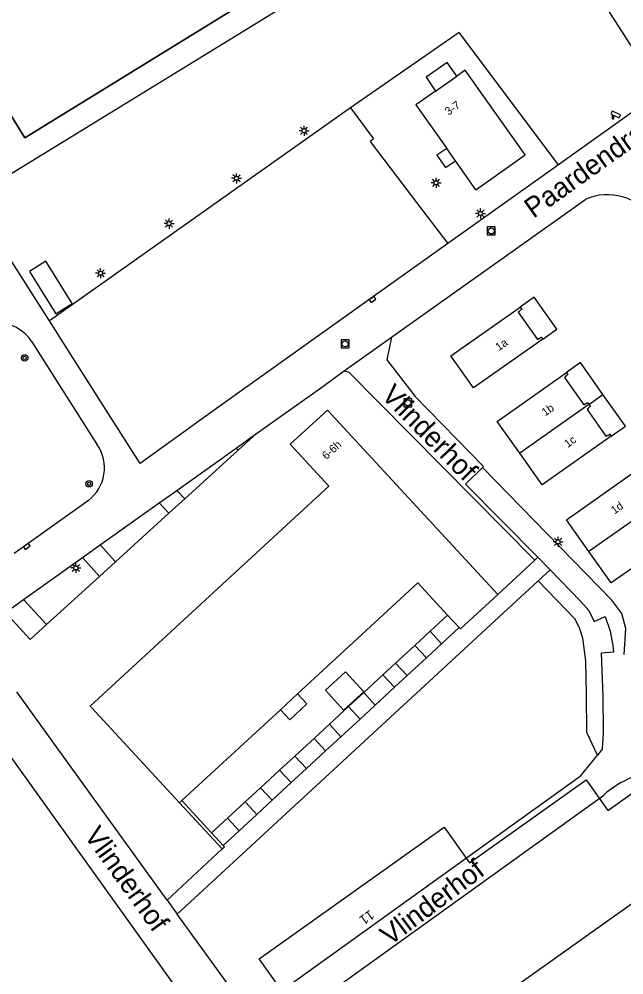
# Model space of a CAD drawing. Extents: x 141000 to 143000, y 400580 to 403500.
# Drawn here: x 141073.5 to 141149.1, y 403024.1 to 403143.4 of the extents above; entities that cross this region are included whole.
import ezdxf

# ---------------------------------------------------------------- set-up
doc = ezdxf.new("R2010")
doc.units = 0
for name, color, linetype in [('gg-afsc-hekwerk', 7, 'Continuous'), ('gg-afsc-muur', 7, 'Continuous'), ('gg-anno-huisnummerreeks BGT', 7, 'Continuous'), ('gg-anno-openbare ruimte label', 7, 'Continuous'), ('gg-bbg-bijgebouw', 7, 'Continuous'), ('gg-bbg-hoofdgebouw', 7, 'Continuous'), ('gg-bbg-luifel en loopbrug', 7, 'Continuous'), ('gg-bbg-tussenscheiding', 7, 'Continuous'), ('gg-knt-verharding', 7, 'Continuous'), ('gg-knt-verharding nz', 7, 'Continuous'), ('gt-anno-plantopografie huisnummer', 7, 'Continuous'), ('gt-bbg-plantopografie pand', 7, 'Continuous'), ('gt-grn-groengrens', 7, 'Continuous'), ('gt-grn-vlakafsluiter', 7, 'Continuous'), ('gt-grn-weggrens', 7, 'Continuous'), ('gt-symb-boom', 7, 'Continuous'), ('gt-symb-camera', 7, 'Continuous'), ('gt-symb-kolk', 7, 'Continuous'), ('gt-symb-lichtmast', 7, 'Continuous'), ('gt-symb-rioolschacht', 7, 'Continuous'), ('gx-grn-maaiveld', 7, 'Continuous')]:
    doc.layers.add(name, color=color, linetype=linetype)

# ---------------------------------------------------------------- blocks, each defined once
blk = doc.blocks.new('gt0-RS')
at = {"layer": 'gt-symb-rioolschacht'}
blk.add_lwpolyline([(-0.5, -0.5), (0.5, -0.5), (0.5, 0.5), (-0.5, 0.5)], close=True, dxfattribs=at)
blk.add_circle((0, 0), 0.375, dxfattribs=at)
blk = doc.blocks.new('gt0-LMAST')
at = {"layer": 'gt-symb-lichtmast'}
for p, q in [((-0.18, 0.17), (-0.45, 0.44)), ((-0.01, 0.25), (-0.01, 0.62)), ((0.17, 0.17), (0.44, 0.44)), ((-0.26, 0), (-0.63, 0)), ((-0.18, -0.18), (-0.45, -0.45)), ((-0.01, -0.25), (-0.01, -0.63)), ((0.44, -0.45), (0.17, -0.18)), ((0.24, 0), (0.62, 0))]:
    blk.add_line(p, q, dxfattribs=at)
blk.add_circle((-0.01, 0), 0.25, dxfattribs=at)
blk = doc.blocks.new('gt0-KOLK')
at = {"layer": 'gt-symb-kolk'}
blk.add_lwpolyline([(0, 0), (0.37, 0), (0.37, 0.4), (-0.38, 0.4), (-0.38, 0), (0, 0)], dxfattribs=at)
blk = doc.blocks.new('gt0-BOOM')
at = {"layer": 'gt-symb-boom'}
for radius in [0.4, 0.2]:
    blk.add_circle((0, 0), radius, dxfattribs=at)
blk = doc.blocks.new('gt0-CAMERA')
at = {"layer": 'gt-symb-camera'}
for points in [[(0.07, 0.48), (0.75, 0.16), (0.92, 0.51), (-0.12, 1), (-0.28, 0.65), (-0.07, 0.55)], [(0.07, 0.48), (0.07, 0), (-0.07, 0), (-0.07, 0.55)]]:
    blk.add_lwpolyline(points, dxfattribs=at)

msp = doc.modelspace()

# ---------------------------------------------------------------- linework, layer by layer
at = {"layer": 'gg-afsc-hekwerk'}
msp.add_lwpolyline([(141060.06, 403151.69), (141094.93, 403173.23), (141109.35, 403150.25), (141074.26, 403128.6), (141060.06, 403151.69)], dxfattribs=at)
at = {"layer": 'gg-afsc-muur'}
for p, q in [((141093.58, 403045.56), (141098.89, 403039.8)), ((141097.58, 403041.82), (141093.87, 403045.84))]:
    msp.add_line(p, q, dxfattribs=at)
msp.add_lwpolyline([(141098.89, 403039.8), (141099.19, 403040.08), (141099.02, 403040.25)], dxfattribs=at)
at = {"layer": 'gg-bbg-bijgebouw'}
for p, q in [((141124.85, 403066.99), (141122.94, 403065.22)), ((141126.3, 403065.42), (141124.85, 403066.99)), ((141122.94, 403065.22), (141124.39, 403063.66)), ((141124.39, 403063.66), (141126.3, 403065.42)), ((141120.55, 403063.01), (141118.97, 403061.56)), ((141121.99, 403061.45), (141120.55, 403063.01)), ((141118.97, 403061.56), (141120.42, 403059.99)), ((141120.42, 403059.99), (141121.99, 403061.45)), ((141116.58, 403059.35), (141114.67, 403057.59)), ((141118.02, 403057.78), (141116.58, 403059.35)), ((141114.67, 403057.59), (141116.11, 403056.02)), ((141116.11, 403056.02), (141118.02, 403057.78)), ((141112.28, 403055.38), (141110.37, 403053.62)), ((141113.72, 403053.82), (141112.28, 403055.38)), ((141110.37, 403053.62), (141111.81, 403052.05)), ((141111.81, 403052.05), (141113.72, 403053.82)), ((141107.98, 403051.41), (141106.07, 403049.65)), ((141109.42, 403049.85), (141107.98, 403051.41)), ((141107.51, 403048.09), (141109.42, 403049.85)), ((141106.07, 403049.65), (141107.51, 403048.09)), ((141103.68, 403047.45), (141101.77, 403045.68)), ((141105.12, 403045.88), (141103.68, 403047.45)), ((141101.77, 403045.68), (141103.21, 403044.12)), ((141103.21, 403044.12), (141105.12, 403045.88)), ((141099.56, 403043.65), (141097.58, 403041.82)), ((141101.01, 403042.08), (141099.56, 403043.65)), ((141099.02, 403040.25), (141097.58, 403041.82)), ((141099.02, 403040.25), (141101.01, 403042.08))]:
    msp.add_line(p, q, dxfattribs=at)
msp.add_lwpolyline([(141128.19, 403136.33), (141126.98, 403138.03), (141124.35, 403136.17), (141125.55, 403134.46)], dxfattribs=at)
at = {"layer": 'gg-bbg-hoofdgebouw'}
for p, q in [((141125.55, 403134.46), (141123.09, 403132.72)), ((141123.09, 403132.72), (141126.93, 403127.3)), ((141128.02, 403125.75), (141126.93, 403127.3)), ((141130.58, 403122.13), (141128.02, 403125.75)), ((141138.92, 403103.49), (141130.27, 403097.39)), ((141147.49, 403091.36), (141138.85, 403085.27)), ((141138.85, 403085.27), (141136.05, 403089.23)), ((141156.14, 403079.11), (141147.46, 403073.02)), ((141147.46, 403073.02), (141144.69, 403076.97)), ((141128.5, 403067.46), (141127.05, 403069.02)), ((141106.17, 403057.19), (141108.3, 403059.16)), ((141082.57, 403057.49), (141093.58, 403045.56)), ((141093.87, 403045.84), (141106.17, 403057.19)), ((141093.58, 403045.56), (141093.87, 403045.84))]:
    msp.add_line(p, q, dxfattribs=at)
for points in [[(141130.58, 403122.13), (141136.74, 403126.48), (141129.25, 403137.08), (141128.19, 403136.33)], [(141130.27, 403097.39), (141127.46, 403101.37), (141136.11, 403107.46)], [(141136.11, 403107.46), (141136.3, 403107.19), (141136.03, 403107), (141136.05, 403106.97), (141135.86, 403106.83), (141138.27, 403103.43), (141138.45, 403103.56), (141138.48, 403103.54), (141138.74, 403103.73), (141138.92, 403103.49)], [(141136.05, 403089.23), (141133.24, 403093.2), (141141.89, 403099.3)], [(141141.89, 403099.3), (141142.08, 403099.04), (141141.82, 403098.85), (141141.85, 403098.81), (141141.65, 403098.67), (141144.05, 403095.26), (141144.24, 403095.4), (141144.27, 403095.38), (141144.53, 403095.56), (141144.7, 403095.32)], [(141144.7, 403095.32), (141144.88, 403095.08), (141144.61, 403094.89), (141144.65, 403094.81), (141144.46, 403094.68), (141146.81, 403091.35), (141147, 403091.49), (141147.05, 403091.42), (141147.32, 403091.6), (141147.49, 403091.36)], [(141133.33, 403071.59), (141112.05, 403094.6), (141107.4, 403090.35), (141112.2, 403085.1), (141082.43, 403057.64), (141082.57, 403057.49)], [(141144.69, 403076.97), (141141.91, 403080.92), (141150.56, 403087.03)], [(141127.05, 403069.02), (141123.34, 403073.04), (141108.3, 403059.16)], [(141133.33, 403071.59), (141128.66, 403067.28), (141128.5, 403067.46)]]:
    msp.add_lwpolyline(points, dxfattribs=at)
at = {"layer": 'gg-bbg-luifel en loopbrug'}
for p, q in [((141144.7, 403095.32), (141146.45, 403096.57)), ((141124.85, 403066.99), (141127.05, 403069.02)), ((141126.3, 403065.42), (141128.5, 403067.46)), ((141120.55, 403063.01), (141122.94, 403065.22)), ((141121.99, 403061.45), (141124.39, 403063.66)), ((141116.58, 403059.35), (141118.97, 403061.56)), ((141118.02, 403057.78), (141120.42, 403059.99)), ((141112.28, 403055.38), (141114.67, 403057.59)), ((141113.72, 403053.82), (141116.11, 403056.02)), ((141107.98, 403051.41), (141110.37, 403053.62)), ((141109.42, 403049.85), (141111.81, 403052.05)), ((141103.68, 403047.45), (141106.07, 403049.65)), ((141105.12, 403045.88), (141107.51, 403048.09)), ((141099.56, 403043.65), (141101.77, 403045.68)), ((141101.01, 403042.08), (141103.21, 403044.12))]:
    msp.add_line(p, q, dxfattribs=at)
for points in [[(141126.93, 403127.3), (141125.7, 403126.44), (141126.8, 403124.89), (141128.02, 403125.75)], [(141076.87, 403113.21), (141074.83, 403111.93), (141078.14, 403106.65), (141080.18, 403107.94), (141076.87, 403113.21)], [(141138.92, 403103.49), (141140.68, 403104.73), (141137.87, 403108.7), (141136.11, 403107.46)], [(141146.45, 403096.57), (141143.64, 403100.54), (141141.89, 403099.3)], [(141147.49, 403091.36), (141149.25, 403092.6), (141146.45, 403096.57)], [(141114.06, 403057.15), (141116.58, 403059.43), (141114.31, 403061.93), (141111.79, 403059.65), (141114.06, 403057.15)], [(141106.17, 403057.19), (141107.33, 403055.94), (141109.46, 403057.91), (141108.3, 403059.16)]]:
    msp.add_lwpolyline(points, dxfattribs=at)
at = {"layer": 'gg-bbg-tussenscheiding'}
for p, q in [((141125.55, 403134.46), (141128.19, 403136.33)), ((141144.7, 403095.32), (141136.05, 403089.23)), ((141153.34, 403083.07), (141144.69, 403076.97))]:
    msp.add_line(p, q, dxfattribs=at)
at = {"layer": 'gg-knt-verharding'}
for p, q in [((141114.91, 403132.36), (141077.33, 403105.75)), ((141114.91, 403132.36), (141117.81, 403128.51)), ((141077.33, 403105.75), (141064.58, 403125.78)), ((141120.06, 403103.73), (141144.3, 403120.95)), ((141075.14, 403103.12), (141083.29, 403090.27)), ((141111.16, 403097.37), (141114.15, 403099.53)), ((141102.78, 403091.4), (141111.16, 403097.37)), ((141100.64, 403089.87), (141102.78, 403091.4)), ((141102.78, 403091.4), (141102.82, 403091.35)), ((141093.24, 403084.59), (141100.64, 403089.87)), ((141100.64, 403089.87), (141100.89, 403089.59)), ((141091.04, 403083.03), (141093.24, 403084.59)), ((141093.24, 403084.59), (141094.23, 403083.54)), ((141082.19, 403083.34), (141072.93, 403076.71)), ((141083.67, 403077.77), (141091.04, 403083.03)), ((141091.04, 403083.03), (141092.24, 403081.72)), ((141081.45, 403076.19), (141083.67, 403077.77)), ((141083.67, 403077.77), (141085.57, 403075.66)), ((141074.09, 403070.94), (141081.45, 403076.19)), ((141081.45, 403076.19), (141083.57, 403073.84)), ((141139.86, 403074.68), (141138.32, 403076.24)), ((141137.94, 403075.86), (141133.33, 403071.59)), ((141138.36, 403073.31), (141093.27, 403031.68)), ((141071.83, 403069.33), (141074.09, 403070.94)), ((141074.09, 403070.94), (141076.97, 403067.83)), ((141071.83, 403069.33), (141074.93, 403065.98)), ((141077.74, 403053.2), (141073.24, 403059.44)), ((141068.88, 403056.29), (141096.13, 403018.32)), ((141092.01, 403033.43), (141077.74, 403053.2)), ((141143.59, 403048.84), (141145.78, 403051.53)), ((141143.59, 403048.84), (141104.67, 403020.9)), ((141107, 403018.12), (141146.54, 403046.54)), ((141098.89, 403039.8), (141092.01, 403033.43)), ((141092.01, 403033.43), (141093.27, 403031.68)), ((141100.29, 403021.95), (141093.27, 403031.68))]:
    msp.add_line(p, q, dxfattribs=at)
for points in [[(141054.55, 403150.07), (141057.4, 403145.7), (141059.93, 403147.32), (141056.4, 403152.91), (141094.62, 403176.46), (141102.17, 403164.21), (141102.7, 403164.56), (141105.03, 403160.96), (141104.42, 403160.54), (141111.86, 403148.25), (141072.07, 403123.82), (141069, 403128.42), (141064.58, 403125.78)], [(141109.35, 403150.25), (141094.93, 403173.23), (141060.06, 403151.69), (141074.26, 403128.6), (141109.35, 403150.25)], [(141117.81, 403128.51), (141117.37, 403128.17), (141123.96, 403119.48), (141127.09, 403115.4)], [(141127.09, 403115.4), (141099.07, 403095.42), (141096.87, 403093.85), (141088.65, 403087.96), (141084.42, 403094.61), (141079.92, 403101.67), (141077.33, 403105.75)], [(141120.06, 403103.73), (141119.47, 403100.9), (141123.01, 403096.3), (141131.54, 403087.55), (141131.42, 403087.43)], [(141114.15, 403099.53), (141114.66, 403099.38), (141137.94, 403075.86)], [(141138.32, 403076.24), (141129.3, 403085.38), (141131.42, 403087.43)], [(141149.09, 403064.08), (141149.3, 403067.33), (141148.8, 403069.23), (141147.56, 403070.86), (141131.42, 403087.43)], [(141139.86, 403074.68), (141143.66, 403070.75), (141144.7, 403069.57), (141145.33, 403068.22), (141146.74, 403068.83), (141147.36, 403067.01), (141147.68, 403065.22), (141147.76, 403064.39), (141146.21, 403064.24), (141146.44, 403058.9), (141146.47, 403054.3), (141146.33, 403052.28), (141145.78, 403051.53)], [(141145.78, 403051.53), (141144.44, 403054.34), (141144.39, 403059.08), (141144.31, 403063.28), (141143.94, 403066.12), (141143.51, 403067.41), (141142.94, 403068.53), (141138.36, 403073.31)]]:
    msp.add_lwpolyline(points, dxfattribs=at)
for centre, radius, start, end in [((141147.02, 403114.65), 6.86, 35.0308, 113.3003), ((141070.78, 403100.35), 5.17, 32.3901, 93.3858), ((141079.12, 403087.38), 5.08, 307.2717, 34.682), ((141154.64, 403037.5), 12.14, 112.4125, 131.8589)]:
    msp.add_arc(centre, radius, start, end, dxfattribs=at)
at = {"layer": 'gg-knt-verharding nz'}
for p, q in [((141137.94, 403075.86), (141138.32, 403076.24)), ((141138.36, 403073.31), (141139.86, 403074.68))]:
    msp.add_line(p, q, dxfattribs=at)
at = {"layer": 'gt-bbg-plantopografie pand'}
for points in [[(141103.5, 403026.08), (141126.6, 403042.51), (141129.76, 403038.07), (141144.33, 403048.44), (141147.07, 403044.6), (141182.03, 403069.48), (141191.21, 403056.56), (141176.68, 403046.23), (141188.02, 403030.29), (141202.4, 403040.52), (141211.54, 403027.68), (141185.2, 403008.94)], [(141176.6, 403022.24), (141165.33, 403038.08), (141154.34, 403030.27), (141151.63, 403034.08), (141133.43, 403021.13)], [(141112.74, 403013.09), (141103.5, 403026.08)]]:
    msp.add_lwpolyline(points, dxfattribs=at)
at = {"layer": 'gt-grn-groengrens'}
for p, q in [((141094.23, 403083.54), (141100.89, 403089.59)), ((141085.57, 403075.66), (141092.24, 403081.72)), ((141076.97, 403067.83), (141083.57, 403073.84))]:
    msp.add_line(p, q, dxfattribs=at)
at = {"layer": 'gt-grn-vlakafsluiter'}
for p, q in [((141100.89, 403089.59), (141102.82, 403091.35)), ((141092.24, 403081.72), (141094.23, 403083.54)), ((141083.57, 403073.84), (141085.57, 403075.66)), ((141074.93, 403065.98), (141076.97, 403067.83))]:
    msp.add_line(p, q, dxfattribs=at)
at = {"layer": 'gt-grn-weggrens'}
msp.add_line((141114.15, 403099.53), (141120.06, 403103.73), dxfattribs=at)
at = {"layer": 'gx-grn-maaiveld'}
for p, q in [((141153.65, 403134.34), (141093.07, 403229.33)), ((141153.65, 403134.34), (141140.88, 403125.24)), ((141140.88, 403125.24), (141127.09, 403115.4))]:
    msp.add_line(p, q, dxfattribs=at)
msp.add_lwpolyline([(141140.88, 403125.24), (141128.49, 403141.76), (141114.91, 403132.36)], dxfattribs=at)

# ---------------------------------------------------------------- block references
at = {"layer": 'gt-symb-boom'}
for p in [(141074.24, 403101.13), (141082.29, 403085.41)]:
    msp.add_blockref('gt0-BOOM', p, dxfattribs=at)
at = {"layer": 'gt-symb-camera'}
msp.add_blockref('gt0-CAMERA', (141147.7, 403130.96), dxfattribs=at)
at = {"layer": 'gt-symb-kolk'}
for p, rotation in [((141117.55, 403108.59), -144.51016483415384), ((141074.38, 403077.75), -144.41166614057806)]:
    msp.add_blockref('gt0-KOLK', p, dxfattribs=dict(at, rotation=rotation))
at = {"layer": 'gt-symb-lichtmast'}
for p in [(141109.13, 403129.5), (141100.69, 403123.56), (141125.61, 403123), (141131.16, 403119.17), (141092.27, 403117.9), (141083.72, 403111.71), (141140.85, 403078.16), (141080.63, 403074.9)]:
    msp.add_blockref('gt0-LMAST', p, dxfattribs=at)
at = {"layer": 'gt-symb-rioolschacht'}
for p in [(141132.5, 403116.99), (141114.24, 403102.88), (141122.09, 403095.51)]:
    msp.add_blockref('gt0-RS', p, dxfattribs=at)

# ---------------------------------------------------------------- texts
at = {"layer": 'gg-anno-huisnummerreeks BGT'}
for s, rotation, p in [('3-7', 35.2, (141127.15, 403131.36)), ('1a', 35.3, (141133.45, 403101.96)), ('1b', 35.1, (141139.23, 403093.81)), ('6-6h', 42.4, (141111.91, 403088.37)), ('1c', 35.3, (141142.05, 403089.87)), ('1d', 35.2, (141147.88, 403081.56))]:
    msp.add_text(s, height=1, rotation=rotation, dxfattribs=at).set_placement(p)
at = {"layer": 'gg-anno-openbare ruimte label'}
for s, rotation, p in [('Paardendraf', 35.5, (141137.77, 403118.49)), ('Vlinderhof', 314.4, (141118.64, 403096.31)), ('Vlinderhof', 305.7, (141081.57, 403041.47)), ('Vlinderhof', 36.9, (141119.84, 403027.65))]:
    msp.add_text(s, height=2.5, rotation=rotation, dxfattribs=at).set_placement(p)
at = {"layer": 'gt-anno-plantopografie huisnummer'}
msp.add_text('11', height=1.2, rotation=215.427, dxfattribs=at).set_placement((141117.36, 403032.25))

doc.saveas('drawing.dxf')
